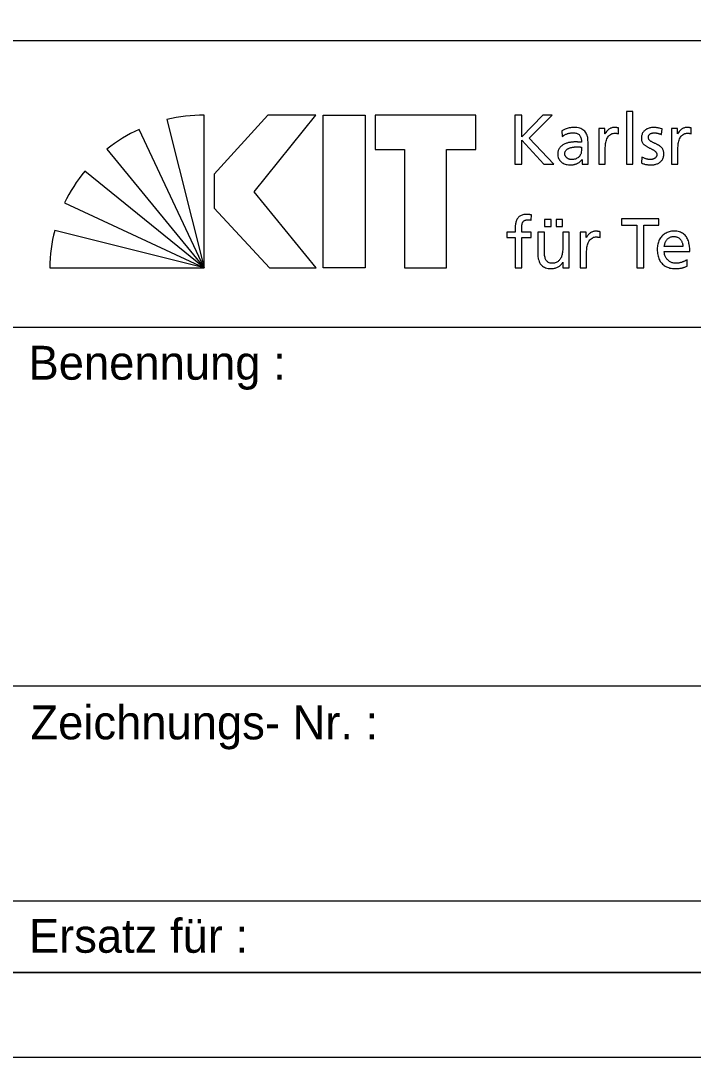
# Model space of a CAD drawing. Extents: x 0 to 59.5, y 0 to 42.1.
# Drawn here: x 55.033 to 57.016, y 0 to 3.058 of the extents above; entities that cross this region are included whole.
import ezdxf

# ---------------------------------------------------------------- set-up
doc = ezdxf.new("R2010")
doc.units = 0
doc.layers.add('90_Plankopf', color=7, linetype='Continuous')

msp = doc.modelspace()

# ---------------------------------------------------------------- linework, layer by layer
at = {"layer": '90_Plankopf'}
for p, q in [((50.306, 2.9995), (59.2, 2.9995)), ((50.306, 2.9995), (59.2, 2.9995)), ((55.4637, 2.7666), (55.574, 2.3293)), ((55.574, 2.3293), (55.574, 2.7792)), ((56.4905, 2.7793), (56.4905, 2.6353)), ((55.574, 2.3293), (55.3817, 2.7376)), ((56.629, 2.7331), (56.63, 2.7166)), ((56.7963, 2.7242), (56.7963, 2.7416)), ((56.9228, 2.722), (56.9245, 2.7389)), ((57.0106, 2.7242), (57.0106, 2.7416)), ((56.7059, 2.6559), (56.7059, 2.6995)), ((55.2872, 2.6793), (55.574, 2.3293)), ((56.6865, 2.6854), (56.6865, 2.6761)), ((56.4905, 2.6353), (56.5111, 2.6353)), ((56.5753, 2.6353), (56.6054, 2.6353)), ((56.8649, 2.6559), (56.8638, 2.6386)), ((55.574, 2.3293), (55.2217, 2.6143)), ((55.162, 2.5207), (55.574, 2.3293)), ((56.5387, 2.4696), (56.5395, 2.4853)), ((55.574, 2.3293), (55.1329, 2.4394)), ((56.7413, 2.4182), (56.7413, 2.4356)), ((56.9853, 2.392), (56.9308, 2.392)), ((56.9308, 2.3776), (57.0059, 2.3776)), ((55.1182, 2.3293), (55.574, 2.3293)), ((56.9979, 2.3337), (56.9979, 2.353)), ((55.0001, 2.1535), (59.2, 2.1535)), ((55.0001, 1.096), (59.2, 1.096)), ((55.0001, 0.4615), (59.2, 0.4615)), ((59.2, 0.25), (50.306, 0.25)), ((50.89, 0.25), (59.2, 0.25)), ((50.89, 0.25), (59.2, 0.25))]:
    msp.add_line(p, q, dxfattribs=at)
for points in [[(0, 0), (59.45, 0), (59.45, 42.05), (0, 42.05)], [(1.25, 0.25), (59.2, 0.25), (59.2, 41.8), (1.25, 41.8)], [(55.9033, 2.7793), (55.7618, 2.7793), (55.6036, 2.6049), (55.6036, 2.5046), (55.7669, 2.3293), (55.9042, 2.3293), (55.7211, 2.5531)], [(56.0485, 2.7793), (56.0485, 2.3293), (55.9251, 2.3293), (55.9251, 2.7793)], [(56.0781, 2.7793), (56.0781, 2.678), (56.1651, 2.678), (56.1651, 2.3293), (56.2885, 2.3293), (56.2885, 2.678), (56.3755, 2.678), (56.3755, 2.7793)]]:
    msp.add_lwpolyline(points, close=True, dxfattribs=at)
for points in [[(56.819, 2.6353), (56.8384, 2.6353), (56.8384, 2.79), (56.819, 2.79), (56.819, 2.6353)], [(56.6054, 2.6353), (56.5324, 2.7112), (56.6, 2.7793), (56.5726, 2.7793), (56.5111, 2.716), (56.5111, 2.7793), (56.4905, 2.7793)], [(56.7561, 2.7242), (56.7557, 2.7242), (56.7557, 2.7405), (56.7375, 2.7405), (56.7375, 2.6353), (56.7569, 2.6353), (56.7569, 2.6832)], [(56.9703, 2.7242), (56.9699, 2.7242), (56.9699, 2.7405), (56.9518, 2.7405), (56.9518, 2.6353), (56.9712, 2.6353), (56.9712, 2.6832)], [(56.5111, 2.6353), (56.5111, 2.7059), (56.5753, 2.6353)], [(56.6882, 2.6489), (56.6886, 2.6489), (56.6886, 2.6353), (56.7067, 2.6353)], [(56.5777, 2.4713), (56.5777, 2.4506), (56.5971, 2.4506), (56.5971, 2.4713), (56.5777, 2.4713)], [(56.6115, 2.4713), (56.6115, 2.4506), (56.6309, 2.4506), (56.6309, 2.4713), (56.6115, 2.4713)], [(56.8495, 2.3293), (56.8701, 2.3293), (56.8701, 2.4552), (56.9149, 2.4552), (56.9149, 2.4733), (56.8047, 2.4733), (56.8047, 2.4552), (56.8495, 2.4552), (56.8495, 2.3293)], [(56.4912, 2.4443), (56.4912, 2.4346), (56.4665, 2.4346), (56.4665, 2.4189), (56.4912, 2.4189), (56.4912, 2.3293), (56.5106, 2.3293), (56.5106, 2.4189), (56.5385, 2.4189), (56.5385, 2.4346), (56.5106, 2.4346), (56.5106, 2.4459)], [(56.5771, 2.3801), (56.5771, 2.4346), (56.5577, 2.4346), (56.5577, 2.372)], [(56.6507, 2.3293), (56.6507, 2.4346), (56.6313, 2.4346), (56.6313, 2.3859)], [(56.7011, 2.4182), (56.7007, 2.4182), (56.7007, 2.4346), (56.6825, 2.4346), (56.6825, 2.3293), (56.7019, 2.3293), (56.7019, 2.3772)], [(56.6316, 2.346), (56.632, 2.346), (56.632, 2.3293), (56.6507, 2.3293)]]:
    msp.add_lwpolyline(points, dxfattribs=at)
for centre, start, end in [((55.5724, 2.3028), 89.8053, 103.1895), ((55.5831, 2.3059), 115.0126, 128.3968), ((55.5908, 2.3131), 140.7898, 154.174), ((55.5946, 2.3219), 165.7222, 179.1064)]:
    msp.add_arc(centre, 0.4764, start, end, dxfattribs=at)
for points in [[(56.7059, 2.6995), (56.706, 2.709), (56.7045, 2.717), (56.7017, 2.7235), (56.6988, 2.73), (56.6942, 2.7348), (56.688, 2.7381), (56.6817, 2.7413), (56.6736, 2.743), (56.6636, 2.743), (56.6569, 2.743), (56.6507, 2.742), (56.6449, 2.7402), (56.6391, 2.7384), (56.6338, 2.7361), (56.629, 2.7331)], [(56.63, 2.7166), (56.6326, 2.7188), (56.6356, 2.7207), (56.639, 2.7223), (56.6423, 2.7239), (56.6458, 2.7251), (56.6495, 2.726), (56.6532, 2.7269), (56.6568, 2.7273), (56.6605, 2.7273), (56.667, 2.7273), (56.6721, 2.7263), (56.6759, 2.7243), (56.6797, 2.7222), (56.6824, 2.7191), (56.6841, 2.7151), (56.6858, 2.711), (56.6865, 2.7059), (56.6865, 2.6999)], [(56.7963, 2.7416), (56.795, 2.7418), (56.7937, 2.7421), (56.7925, 2.7423), (56.7912, 2.7425), (56.7899, 2.7427), (56.7885, 2.7428), (56.7871, 2.7429), (56.7854, 2.743), (56.7835, 2.743), (56.7798, 2.743), (56.7761, 2.7422), (56.7726, 2.7406), (56.7691, 2.739), (56.7659, 2.7368), (56.763, 2.7339), (56.7601, 2.7311), (56.7578, 2.7279), (56.7561, 2.7242)], [(56.7569, 2.6832), (56.7569, 2.692), (56.7581, 2.6996), (56.7605, 2.706), (56.7629, 2.7124), (56.7662, 2.7174), (56.7705, 2.7208), (56.7747, 2.7243), (56.7798, 2.726), (56.7856, 2.7261), (56.7873, 2.7261), (56.789, 2.726), (56.7909, 2.7257), (56.7927, 2.7254), (56.7945, 2.7249), (56.7963, 2.7242)], [(56.9245, 2.7389), (56.9207, 2.74), (56.9169, 2.741), (56.913, 2.7418), (56.9091, 2.7426), (56.9049, 2.743), (56.9004, 2.743), (56.8951, 2.743), (56.8903, 2.7423), (56.8858, 2.741), (56.8813, 2.7397), (56.8774, 2.7377), (56.874, 2.735), (56.8706, 2.7323), (56.868, 2.729), (56.8661, 2.7249), (56.8642, 2.7208), (56.8632, 2.7161), (56.8632, 2.7106), (56.8632, 2.7064), (56.8641, 2.7028), (56.8658, 2.6997), (56.8674, 2.6966), (56.8695, 2.694), (56.8723, 2.6917), (56.875, 2.6895), (56.8779, 2.6875), (56.8812, 2.6857), (56.8844, 2.684), (56.8876, 2.6824), (56.8909, 2.6809), (56.8941, 2.6793), (56.8971, 2.6777), (56.8998, 2.6761), (56.9025, 2.6745), (56.9047, 2.6727), (56.9063, 2.6706), (56.9079, 2.6686), (56.9088, 2.6663), (56.9088, 2.6636), (56.9088, 2.6607), (56.9082, 2.6584), (56.907, 2.6564), (56.9058, 2.6545), (56.9042, 2.6529), (56.9022, 2.6518), (56.9003, 2.6506), (56.8982, 2.6498), (56.8959, 2.6493), (56.8935, 2.6487), (56.8912, 2.6485), (56.889, 2.6485), (56.8871, 2.6485), (56.8847, 2.6488), (56.882, 2.6493), (56.8792, 2.6499), (56.8763, 2.6507), (56.8733, 2.6518), (56.8703, 2.6529), (56.8675, 2.6543), (56.8649, 2.6559)], [(56.8638, 2.6386), (56.8683, 2.6363), (56.873, 2.6347), (56.8779, 2.6339), (56.8828, 2.6331), (56.8877, 2.6327), (56.8927, 2.6328), (56.8975, 2.6328), (56.902, 2.6335), (56.9064, 2.6348), (56.9107, 2.6361), (56.9147, 2.6381), (56.9181, 2.6408), (56.9216, 2.6435), (56.9243, 2.6469), (56.9264, 2.651), (56.9284, 2.6551), (56.9294, 2.66), (56.9295, 2.6656), (56.9294, 2.6704), (56.9286, 2.6745), (56.9269, 2.6778), (56.9253, 2.6811), (56.9231, 2.684), (56.9204, 2.6863), (56.9177, 2.6886), (56.9147, 2.6906), (56.9115, 2.6922), (56.9083, 2.6939), (56.905, 2.6954), (56.9018, 2.6968), (56.8986, 2.6983), (56.8956, 2.6998), (56.8929, 2.7013), (56.8902, 2.7029), (56.888, 2.7047), (56.8864, 2.7068), (56.8847, 2.7089), (56.8839, 2.7115), (56.8838, 2.7145), (56.8839, 2.7174), (56.8848, 2.7198), (56.8865, 2.7217), (56.8882, 2.7236), (56.8904, 2.725), (56.8932, 2.7259), (56.896, 2.7269), (56.8991, 2.7273), (56.9024, 2.7273), (56.9036, 2.7273), (56.9051, 2.7271), (56.9069, 2.7269), (56.9088, 2.7266), (56.9107, 2.7261), (56.9127, 2.7256), (56.9148, 2.7251), (56.9167, 2.7246), (56.9185, 2.7239), (56.9203, 2.7233), (56.9217, 2.7226), (56.9228, 2.722)], [(57.0106, 2.7416), (57.0092, 2.7418), (57.0079, 2.7421), (57.0067, 2.7423), (57.0055, 2.7425), (57.0041, 2.7427), (57.0027, 2.7428), (57.0013, 2.7429), (56.9997, 2.743), (56.9978, 2.743), (56.994, 2.743), (56.9904, 2.7422), (56.9868, 2.7406), (56.9833, 2.739), (56.9801, 2.7368), (56.9773, 2.7339), (56.9744, 2.7311), (56.9721, 2.7279), (56.9703, 2.7242)], [(56.9712, 2.6832), (56.9712, 2.692), (56.9724, 2.6996), (56.9747, 2.706), (56.9771, 2.7124), (56.9804, 2.7174), (56.9847, 2.7208), (56.989, 2.7243), (56.994, 2.726), (56.9998, 2.7261), (57.0015, 2.7261), (57.0033, 2.726), (57.0051, 2.7257), (57.007, 2.7254), (57.0088, 2.7249), (57.0106, 2.7242)], [(56.6865, 2.6999), (56.684, 2.7), (56.6817, 2.7001), (56.6795, 2.7001), (56.6773, 2.7002), (56.6751, 2.7003), (56.6729, 2.7003), (56.6708, 2.7003), (56.6684, 2.7003), (56.6659, 2.7003), (56.6618, 2.7003), (56.6576, 2.6999), (56.6531, 2.6992), (56.6487, 2.6985), (56.6443, 2.6973), (56.64, 2.6957), (56.6358, 2.6941), (56.6319, 2.6919), (56.6284, 2.6892), (56.625, 2.6866), (56.6222, 2.6833), (56.6201, 2.6794), (56.6181, 2.6755), (56.6171, 2.6709), (56.617, 2.6656), (56.6171, 2.658), (56.6187, 2.6518), (56.6219, 2.6469), (56.6252, 2.6421), (56.6297, 2.6385), (56.6355, 2.6362), (56.6413, 2.6339), (56.6479, 2.6328), (56.6556, 2.6328), (56.66, 2.6328), (56.664, 2.6334), (56.6675, 2.6344), (56.671, 2.6355), (56.6741, 2.6368), (56.6768, 2.6384), (56.6795, 2.6401), (56.6818, 2.6419), (56.6837, 2.6437), (56.6855, 2.6455), (56.687, 2.6472), (56.6882, 2.6489)], [(56.6865, 2.6761), (56.6865, 2.6709), (56.6854, 2.6661), (56.6832, 2.662), (56.681, 2.6578), (56.6777, 2.6546), (56.6733, 2.6522), (56.669, 2.6498), (56.6636, 2.6485), (56.6572, 2.6485), (56.655, 2.6485), (56.6527, 2.6489), (56.6504, 2.6496), (56.6481, 2.6503), (56.646, 2.6514), (56.6441, 2.6529), (56.6422, 2.6543), (56.6406, 2.6561), (56.6394, 2.6582), (56.6383, 2.6604), (56.6377, 2.6628), (56.6376, 2.6656), (56.6377, 2.6693), (56.6386, 2.6724), (56.6404, 2.6749), (56.6422, 2.6773), (56.6446, 2.6793), (56.6475, 2.6807), (56.6503, 2.6822), (56.6534, 2.6833), (56.6567, 2.6841), (56.66, 2.6848), (56.6632, 2.6853), (56.6663, 2.6855), (56.6694, 2.6858), (56.672, 2.6859), (56.6741, 2.6858), (56.6762, 2.6858), (56.6783, 2.6858), (56.6803, 2.6856), (56.6824, 2.6855), (56.6845, 2.6855), (56.6865, 2.6854)], [(56.7067, 2.6353), (56.7066, 2.6363), (56.7065, 2.6377), (56.7063, 2.6393), (56.7062, 2.6411), (56.7061, 2.6433), (56.7061, 2.646), (56.706, 2.6486), (56.7059, 2.652), (56.7059, 2.6559)], [(56.5395, 2.4853), (56.5375, 2.4856), (56.5355, 2.4859), (56.5334, 2.4862), (56.5312, 2.4864), (56.529, 2.4866), (56.5265, 2.4866), (56.5194, 2.4865), (56.5135, 2.4855), (56.5089, 2.4836), (56.5043, 2.4816), (56.5007, 2.4787), (56.4981, 2.475), (56.4955, 2.4713), (56.4937, 2.4668), (56.4927, 2.4616), (56.4917, 2.4565), (56.4912, 2.4507), (56.4912, 2.4443)], [(56.5106, 2.4459), (56.5106, 2.4495), (56.5108, 2.4528), (56.5112, 2.4558), (56.5116, 2.4588), (56.5125, 2.4615), (56.5137, 2.4637), (56.515, 2.466), (56.5169, 2.4677), (56.5194, 2.469), (56.5219, 2.4702), (56.5252, 2.4709), (56.5294, 2.4709), (56.5311, 2.4709), (56.5328, 2.4708), (56.5344, 2.4706), (56.5361, 2.4703), (56.5375, 2.47), (56.5387, 2.4696)], [(56.7413, 2.4356), (56.74, 2.4359), (56.7387, 2.4361), (56.7375, 2.4363), (56.7363, 2.4365), (56.7349, 2.4367), (56.7335, 2.4368), (56.7321, 2.437), (56.7304, 2.437), (56.7286, 2.437), (56.7248, 2.437), (56.7212, 2.4362), (56.7176, 2.4346), (56.7141, 2.433), (56.7109, 2.4308), (56.7081, 2.428), (56.7052, 2.4252), (56.7029, 2.4219), (56.7011, 2.4182)], [(56.7019, 2.3772), (56.702, 2.386), (56.7032, 2.3937), (56.7055, 2.4001), (56.7079, 2.4065), (56.7112, 2.4114), (56.7155, 2.4148), (56.7198, 2.4183), (56.7248, 2.4201), (56.7306, 2.4201), (56.7323, 2.4201), (56.7341, 2.42), (56.7359, 2.4197), (56.7378, 2.4195), (56.7396, 2.419), (56.7413, 2.4182)], [(57.0059, 2.3776), (57.006, 2.3861), (57.0052, 2.394), (57.0036, 2.4012), (57.002, 2.4084), (56.9995, 2.4146), (56.9959, 2.42), (56.9923, 2.4254), (56.9875, 2.4295), (56.9815, 2.4325), (56.9756, 2.4355), (56.9682, 2.437), (56.9595, 2.437), (56.952, 2.437), (56.9453, 2.4357), (56.9392, 2.4331), (56.9332, 2.4305), (56.928, 2.4269), (56.9237, 2.4221), (56.9194, 2.4174), (56.916, 2.4118), (56.9137, 2.4052), (56.9114, 2.3988), (56.9102, 2.3916), (56.9102, 2.3838), (56.9102, 2.3752), (56.9113, 2.3674), (56.9134, 2.3604), (56.9156, 2.3535), (56.919, 2.3475), (56.9234, 2.3425), (56.9279, 2.3375), (56.9335, 2.3336), (56.9404, 2.3309), (56.9473, 2.3282), (56.9553, 2.3269), (56.9647, 2.3268), (56.9704, 2.3269), (56.9753, 2.3273), (56.9793, 2.328), (56.9834, 2.3288), (56.9869, 2.3297), (56.9898, 2.3307), (56.9928, 2.3317), (56.9954, 2.3327), (56.9979, 2.3337)], [(56.9308, 2.392), (56.9312, 2.3955), (56.932, 2.3989), (56.9332, 2.4024), (56.9344, 2.4058), (56.9361, 2.4089), (56.9384, 2.4118), (56.9406, 2.4147), (56.9434, 2.417), (56.9469, 2.4187), (56.9503, 2.4204), (56.9543, 2.4213), (56.9591, 2.4213), (56.9633, 2.4213), (56.967, 2.4206), (56.9702, 2.419), (56.9735, 2.4175), (56.9762, 2.4154), (56.9785, 2.4127), (56.9807, 2.4101), (56.9824, 2.4069), (56.9835, 2.4034), (56.9847, 2.3999), (56.9853, 2.3961), (56.9853, 2.392)], [(56.6313, 2.3859), (56.6313, 2.3794), (56.6307, 2.3736), (56.6295, 2.3683), (56.6282, 2.363), (56.6263, 2.3584), (56.6236, 2.3546), (56.621, 2.3507), (56.6177, 2.3478), (56.6137, 2.3457), (56.6096, 2.3436), (56.6049, 2.3426), (56.5994, 2.3425), (56.5938, 2.3429), (56.5893, 2.3444), (56.5861, 2.3473), (56.5828, 2.3501), (56.5805, 2.3542), (56.5791, 2.3597), (56.5777, 2.3651), (56.5771, 2.3719), (56.5771, 2.3801)], [(56.5577, 2.372), (56.5577, 2.3626), (56.5591, 2.3545), (56.5618, 2.3478), (56.5646, 2.341), (56.569, 2.3359), (56.5748, 2.3323), (56.5806, 2.3287), (56.588, 2.3269), (56.5971, 2.3268), (56.602, 2.3269), (56.6068, 2.3276), (56.6113, 2.3291), (56.6158, 2.3307), (56.6198, 2.3329), (56.6233, 2.3357), (56.6268, 2.3386), (56.6296, 2.342), (56.6316, 2.346)], [(56.9979, 2.353), (56.9967, 2.3521), (56.9949, 2.351), (56.9926, 2.3497), (56.9903, 2.3485), (56.9877, 2.3474), (56.9847, 2.3463), (56.9817, 2.3452), (56.9786, 2.3443), (56.9753, 2.3436), (56.972, 2.3429), (56.9687, 2.3426), (56.9655, 2.3425), (56.9608, 2.3426), (56.9565, 2.3434), (56.9523, 2.3451), (56.9482, 2.3468), (56.9445, 2.3492), (56.9413, 2.3523), (56.938, 2.3554), (56.9355, 2.359), (56.9336, 2.3633), (56.9318, 2.3676), (56.9309, 2.3724), (56.9308, 2.3776)]]:
    msp.add_open_spline(points, degree=3, dxfattribs=at)

# ---------------------------------------------------------------- texts
for s, p in [('Benennung :', (55.0557, 1.999)), ('Zeichnungs- Nr. :', (55.0614, 0.9379)), ('Ersatz für :', (55.0569, 0.3084))]:
    msp.add_text(s, height=0.1, dxfattribs=at).set_placement(p)

doc.saveas('drawing.dxf')
